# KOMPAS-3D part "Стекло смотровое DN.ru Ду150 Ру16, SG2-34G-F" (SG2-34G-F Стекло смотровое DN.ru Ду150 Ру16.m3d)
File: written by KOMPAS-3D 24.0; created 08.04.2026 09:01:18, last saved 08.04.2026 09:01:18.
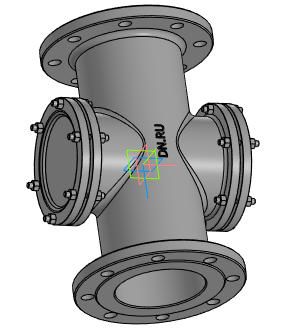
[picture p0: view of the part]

Document properties: Автор: Main; Полное имя файла: D:\DN.ru Аутсерс\Стекло смотровое DN.ru\SG2-34G-F Стекло смотровое DN.ru Ду150 Ру16\SG2-34G-F Стекло смотровое DN.ru Ду150 Ру16.m3d

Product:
- Part/product: Стекло смотровое DN.ru Ду150 Ру16  | designation SG2-34G-F
    Масса: 42
    Раздел спецификации: Прочие изделия
    Примечание: D500-00089

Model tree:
1. Операция без истории:1

Expressions: SG2-34G-F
